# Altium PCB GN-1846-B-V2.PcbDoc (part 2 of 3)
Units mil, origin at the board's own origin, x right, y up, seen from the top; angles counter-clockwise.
Board outline 11621.85 x 2979.29 mil, 2 copper layers (Top, Bottom), stack 12.7 mil thick; 356 components, 252 nets, 1224 pads, 826 vias.
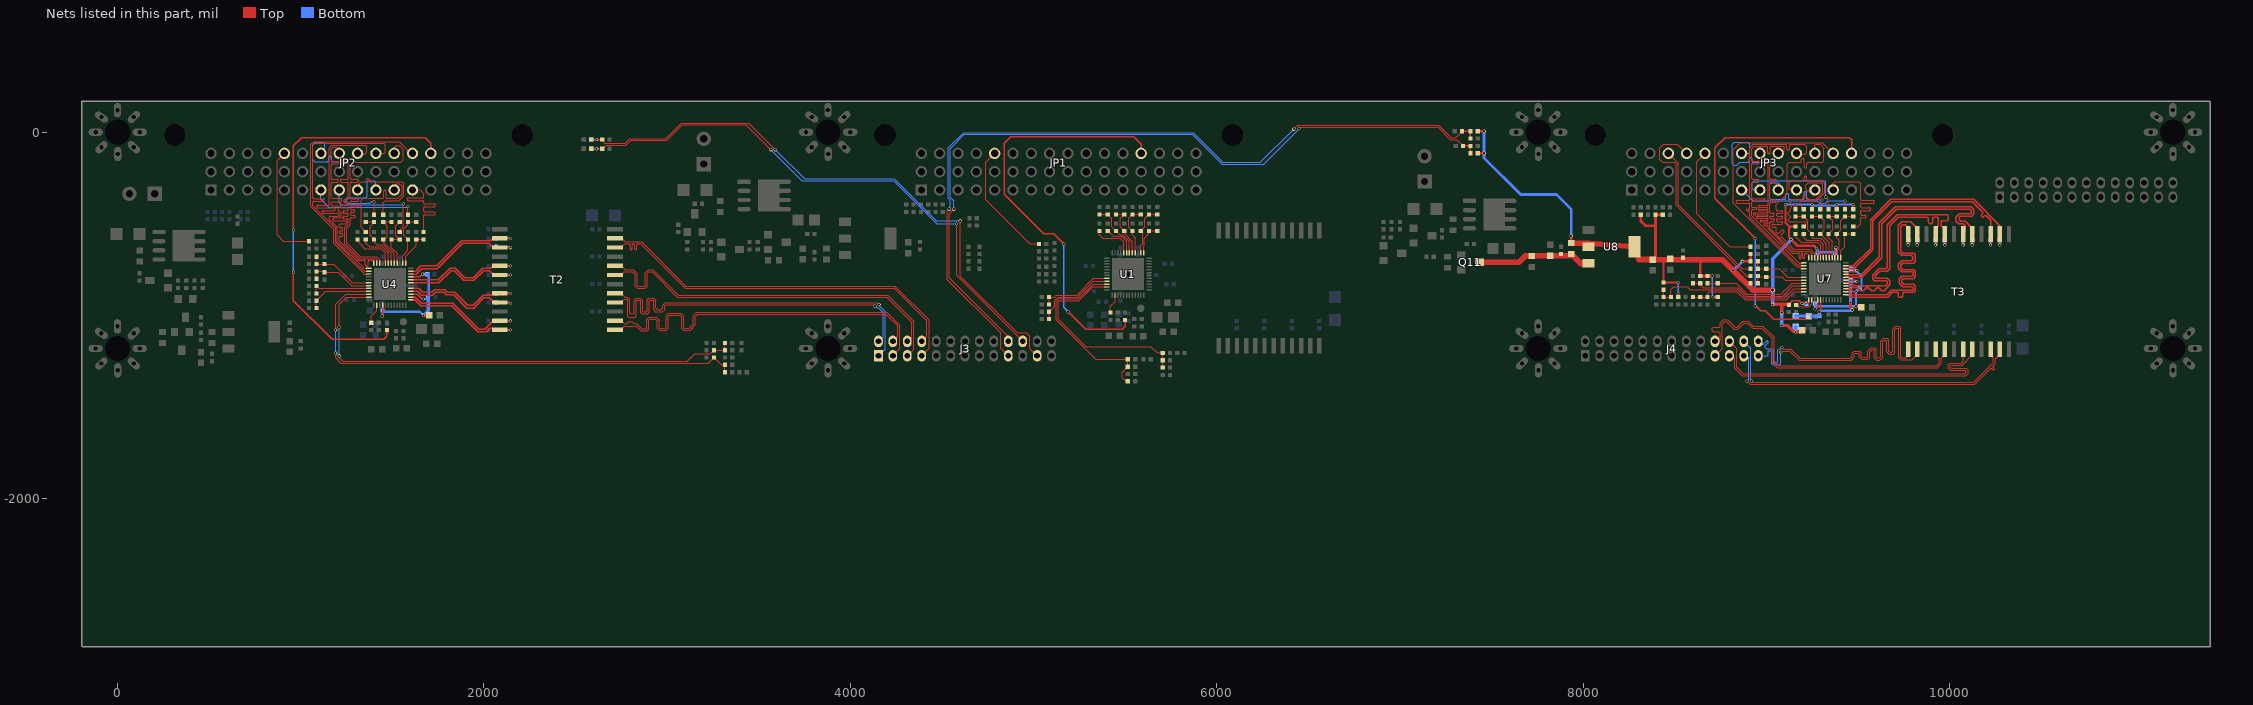
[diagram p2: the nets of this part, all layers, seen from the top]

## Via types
v1: diameter 18, hole 12, Top to Bottom, 786 vias
v2: diameter 24, hole 16, Top to Bottom, 28 vias
v3: diameter 30, hole 20, Top to Bottom, 6 vias
v4: diameter 40, hole 30, Top to Bottom, 6 vias

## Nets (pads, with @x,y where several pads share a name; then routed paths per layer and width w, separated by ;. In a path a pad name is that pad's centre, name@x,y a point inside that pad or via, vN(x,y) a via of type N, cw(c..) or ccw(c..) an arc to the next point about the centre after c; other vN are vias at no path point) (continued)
B_MX1_N: J3.8 T2.22 | length 2112.3
  Top w6: T2.22@2715.76,-629.21 2750,-629.21 2769.21,-610 2792.6,-610 cw(c2792.6,-615.4) 2798,-615.4 2798,-635.5 ccw(c2803.4,-635.5) 2803.4,-640.9 2804.6,-640.9 ccw(c2804.6,-635.5) 2810,-635.5 2810,-615.4 cw(c2815.4,-615.4) 2815.4,-610 2816.6,-610 cw(c2816.6,-615.4) 2822,-615.4 2822,-635.5 ccw(c2827.4,-635.5) 2827.4,-640.9 2828.6,-640.9 ccw(c2828.6,-635.5) 2834,-635.5 2834,-615.4 cw(c2839.4,-615.4) 2839.4,-610 2856.62,-610 3097.62,-851 4238.44,-851 4418,-1030.56 4418,-1113.5 J3.8@4389.76,-1141.73
B_MX1_P: J3.7 T2.23 | length 2109.9
  Top w6: T2.23@2715.76,-579.21 2752.21,-579.21 2772,-599 2861.17,-599 3102.17,-840 4243,-840 4430,-1027 4430,-1180.24 J3.7@4389.76,-1220.47
B_MX2_N: J3.6 T2.19 | length 2003
  Top w6: T2.19@2715.76,-779.21 2750.79,-779.21 2767,-763 2809.09,-763 2825,-778.91 2825,-840.56 2835.44,-851 2879.56,-851 2890,-840.56 2890,-773 2900,-763 2918,-763 3056,-901 4199.44,-901 4335,-1036.56 4335,-1117.76 J3.6@4311.02,-1141.73
B_MX2_P: J3.5 T2.20 | length 2107.2
  Top w6: T2.20@2715.76,-729.21 2749.21,-729.21 2772,-752 2813.65,-752 2836,-774.35 2836,-836 2840,-840 2875,-840 2879,-836 2879,-768.44 2895.44,-752 2922.56,-752 3060.56,-890 4204,-890 4346,-1032 4346,-1185.5 J3.5@4311.02,-1220.47
B_MX3_N: J3.2 T2.16 | length 2043.5
  Top w6: T2.16@2715.76,-929.21 2750.79,-929.21 2767,-913 2778,-913 2785,-920 2785,-1005 2790,-1010 2825,-1010 2830,-1005 2830,-923.4 2835,-918.4 2849.4,-918.4 2856,-925 2856,-986 2860,-990 2895,-990 2901.44,-983.56 2901.44,-923.56 2906.6,-918.4 2923.4,-918.4 2925.56,-920.56 2925.56,-970.56 2936,-981 2974,-981 2986.99,-968.01 2986.99,-948.01 2993,-942 4127,-942 v1(4135,-950)
  Bottom w6: v1(4135,-950) 4143,-958 4151,-958 4179,-986 4179,-1116.28 J3.2@4153.54,-1141.73
B_MX3_P: J3.1 T2.17 | length 2121.5
  Top w6: T2.17@2715.76,-879.21 2749.21,-879.21 2772,-902 2782.56,-902 2796,-915.44 2796,-986 2800,-990 2815,-990 2819,-986 2819,-918.84 2830.44,-907.4 2853.96,-907.4 2867,-920.44 2867,-977 2869,-979 2886,-979 2890.44,-974.56 2890.44,-913.84 2896.89,-907.4 2927.96,-907.4 2936.56,-916 2936.56,-961.56 2945,-970 2965,-970 2975.99,-959.01 2975.99,-943.46 2988.44,-931 4147,-931 v1(4157,-941) ; v1@4159,-939 v1@4160,-940
  Bottom w6: J3.1@4153.54,-1220.47 4190,-1184.02 4190,-981.44 4160,-951.44 4160,-941 v1@4160,-940
B_MX4_N: J3.4 T2.13 | length 1990.4
  Top w6: T2.13@2715.76,-1079.21 2745.79,-1079.21 2767,-1058 2830,-1058 2857,-1085 2890,-1085 2900,-1075 2900,-1025 2905,-1020 2935,-1020 2945,-1030 2945,-1069 2956,-1080 2994,-1080 3005,-1069 3005,-1005 3010,-1000 3070,-1000 3080,-1010 3080,-1070 3090,-1080 3125,-1080 3153,-1052 3153,-1007 3167,-993 4194.44,-993 4259,-1057.56 4259,-1115.02 J3.4@4232.28,-1141.73
B_MX4_P: J3.3 T2.14 | length 2100.2
  Top w6: T2.14@2715.76,-1029.21 2749.21,-1029.21 2767,-1047 2778,-1047 2790,-1035 2808,-1035 2820,-1047 2834.56,-1047 2861.56,-1074 2885,-1074 2889,-1070 2889,-1020.44 2900.44,-1009 2939.56,-1009 2956,-1025.44 2956,-1064.44 2960.56,-1069 2989.44,-1069 2994,-1064.44 2994,-1000.44 3005.44,-989 3074.56,-989 3091,-1005.44 3091,-1065.44 3094.56,-1069 3120.44,-1069 3142,-1047.44 3142,-1002.44 3162.44,-982 4199,-982 4270,-1053 4270,-1182.76 J3.3@4232.28,-1220.47
B_TD1_N: C58.2 T2.3 U4.10 | length 706.2
  Top w8: U4.10@1600.76,-774.09 1630.91,-774.09 1660,-745 1745,-745 1885,-605 2025,-605 2050,-630 2085.05,-630 T2.3@2085.84,-629.21 v1@2144.21,-629.21
  Bottom w8: C58.2@2065,-625 2140,-625 v1(2145,-630)
B_TD1_P: C54.2 T2.2 U4.11 | length 698.8
  Top w8: U4.11@1600.76,-758.34 1626.66,-758.34 1655.42,-729.58 1742.03,-729.58 1879.62,-592 2038,-592 2050.79,-579.21 T2.2@2085.84,-579.21 2144.21,-579.21 v1(2145,-580)
  Bottom w8: C54.2@2065,-580 v1(2145,-580)
B_TD2_N: C57.2 T2.6 U4.7 | length 711
  Top w8: U4.7@1600.76,-821.34 1753.66,-821.34 1820,-755 1836.62,-755 1889.62,-808 1945.38,-808 1998.38,-755 2030,-755 2054.21,-779.21 T2.6@2085.84,-779.21 2145,-779.21 2149.21,-779.21 v1@2150,-780
  Bottom w8: C57.2@2065,-780 v1(2145,-780)
B_TD2_P: C53.2 T2.5 U4.8 | length 700.1
  Top w8: U4.8@1600.76,-805.59 1751.02,-805.59 1814.62,-742 1842,-742 1895,-795 1940,-795 1993,-742 2038,-742 2050.79,-729.21 T2.5@2085.84,-729.21 2144.21,-729.21 v1(2145,-730)
  Bottom w8: C53.2@2065,-730 v1(2145,-730)
B_TD3_N: C52.2 T2.9 U4.4 | length 706.4
  Top w8: U4.4@1600.76,-868.58 1638.58,-868.58 1660,-890 1718.38,-890 1735.38,-873 1779.62,-873 1794.62,-888 1834.62,-888 1906.62,-960 1945,-960 2000,-905 2030,-905 2054.21,-929.21 T2.9@2085.84,-929.21 2139.21,-929.21 v1(2145,-935)
  Bottom w8: C52.2@2065,-930 v1@2140,-930
B_TD3_P: C56.2 T2.8 U4.5 | length 704
  Top w8: U4.5@1600.76,-852.83 1642.83,-852.83 1665,-875 1715,-875 1730,-860 1785,-860 1800,-875 1840,-875 1910,-945 1940,-945 1995,-890 2040,-890 2050.79,-879.21 T2.8@2085.84,-879.21 ; T2.8@2085.05,-880 T2.8@2085.84,-879.21 ; v1@2145.79,-879.21 2145,-879.21 T2.8@2085.84,-879.21
  Bottom w8: C56.2@2065,-880 v1(2145,-880)
B_TD4_N: C55.2 T2.12 U4.1 | length 708.8
  Top w8: U4.1@1600.76,-915.82 1622.44,-915.82 1654.62,-948 1824.62,-948 1966.62,-1090 2015,-1090 2035,-1070 2045,-1070 2054.21,-1079.21 T2.12@2085.84,-1079.21 2144.21,-1079.21 v1(2145,-1080)
  Bottom w8: C55.2@2065,-1080 v1(2145,-1080)
B_TD4_P: C51.2 T2.11 U4.2 | length 716
  Top w8: U4.2@1600.76,-900.08 1625.08,-900.08 1660,-935 1830,-935 1970,-1075 2005,-1075 2050,-1030 2085.05,-1030 T2.11@2085.84,-1029.21 2144.21,-1029.21 v1(2145,-1030)
  Bottom w8: C51.2@2065,-1030 v1(2145,-1030)
BEPHY_CLK: JP2.A13 R73.1 | length 2320.4
  Top w8: v1(960,-765) 960,-920 1171,-1131 1454,-1131 1470,-1115 R73.1@1470,-1080 ; v1(960,-535) 960,-75 1005,-30 1680,-30 1709.84,-59.84 JP2.A13@1709.84,-115.35
  Bottom w8: v1(960,-765) v1(960,-535)
BEPHY_RSTN: JP2.A5 R72.1 | length 650.6
  Top w5: JP2.A5@909.84,-115.35 870,-155.2 870,-560 905,-595 R72.1@1045,-595
BGE0_ENREG: R85.1 U4.38 | length 108.2
  Top w5: R85.1@1385,-1040 1385,-1005 1414.93,-975.07 U4.38@1414.93,-944.17
BGE0_INT_N: R83.1 U4.20 | length 245
  Top w5: R83.1@1310,-585 1310,-595 1350,-635 1440,-635 1462.18,-657.18 U4.20@1462.18,-714.25
BGE0_LED0: R80.1 R81.1 R89.1 U4.34 | length 2694.4
  Top w5: v1@1190,-1200 v1(1190,-1207) 1190,-1232 1218,-1260 3225,-1260 R89.1@3255,-1230 ; v1(1190,-1080) 1190,-940 1245.67,-884.33 U4.34@1370.84,-884.33 ; R89.1@3260,-1235 3295,-1270 R80.1@3315,-1270 R81.1@3315,-1310
  Bottom w5: v1@1190,-1200 v1(1190,-1080)
BGE0_LED1: R75.1 R76.1 R92.1 U4.35 | length 2630.1
  Top w5: v1(1210,-1221) 1210,-1231 1229,-1250 3110,-1250 3150,-1210 3235,-1210 R92.1@3255,-1190 ; v1(1210,-1065) 1210,-940 1249.92,-900.08 U4.35@1370.84,-900.08 ; R92.1@3265,-1190 R76.1@3315,-1190 R75.1@3315,-1150
  Bottom w5: v1@1210,-1215 v1(1210,-1065)
BGE0_LED2: R100.1 R101.1 U4.32 | length 331.2
  Top w5: R101.1@1085,-880 R100.1@1085,-840 1097.83,-852.83 U4.32@1370.84,-852.83
BGE0_PME: R87.1 R88.1 U4.33 | length 347.1
  Top w5: R88.1@1085,-960 R87.1@1085,-920 1136.42,-868.58 U4.33@1370.84,-868.58
BGE0_RXCLK: R64.2 U4.19 | length 221.2
  Top w5: R64.2@1355,-585 1355,-605 1375,-625 1445,-625 1477.93,-657.93 U4.19@1477.93,-714.25
BGE0_RXCTL: R65.2 R93.1 U4.13 | length 204.8
  Top w5: U4.13@1572.41,-702.59 U4.13@1572.41,-714.25 1572.41,-677.59 1630,-620 R93.1@1630,-585 R65.2@1670,-585
BGE0_RXD0: R66.2 R96.1 R98.1 U4.14 | length 299.2
  Top w5: U4.14@1556.67,-714.25 1556.67,-673.33 1585,-645 R98.1@1585,-585 1563,-563 1563,-527 1585,-505 R66.2@1585,-490 R96.1@1630,-490
BGE0_RXD1: R67.2 R102.1 R103.1 U4.16 | length 299.1
  Top w5: U4.16@1525.17,-714.25 1525.17,-660.17 1495,-630 R103.1@1495,-585 R67.2@1540,-585 1519,-564 1519,-511 R102.1@1540,-490
BGE0_RXD2: R68.2 R105.1 R107.1 U4.17 | length 312.1
  Top w5: R105.1@1495,-490 R68.2@1450,-490 1472,-512 1472,-568 1450,-590 1450,-600 1509.42,-659.42 U4.17@1509.42,-714.25
BGE0_RXD3: R70.2 R108.1 R109.1 U4.18 | length 346.3
  Top w5: R108.1@1355,-490 R70.2@1400,-490 1378,-512 1378,-563 R109.1@1400,-585 1400,-600 1415,-615 1449.14,-615 1493.67,-659.53 U4.18@1493.67,-714.25
BMAC_MDC: C66.2 R90.1 R97.2 U4.30 | length 367.8
  Top w5: R90.1@1085,-680 R97.2@1085,-720 C66.2@1130,-720 1180,-720 1281.34,-821.34 U4.30@1370.84,-821.34
BMAC_MDIO: C67.2 R91.1 R99.2 U4.31 | length 357.8
  Top w5: R91.1@1085,-800 R99.2@1085,-760 1125,-760 C67.2@1130,-765 1205,-765 1277.08,-837.08 U4.31@1370.84,-837.08
BPHY105: B5.1 C42.1 C43.1 C44.1 U4.3 U4.9 U4.40 | length 795.5
  Top w8: v1(1445,-1005) 1446.43,-1003.57 U4.40@1446.43,-944.17 ; U4.3@1600.76,-884.33 1634.33,-884.33 1660,-910 v1(1670,-910) ; U4.9@1600.76,-789.84 1650.16,-789.84 v1(1665,-775)
  Top w18: v1(1670,-1000) B5.1@1690.47,-1000
  Bottom w8: v1(1445,-1005) v1@1446.43,-1003.57
  Bottom w12: v1@1446.43,-1003.57 C42.1@1446.43,-973.7 1452.73,-980 1650,-980 v1(1670,-1000) ; v1(1665,-775) C44.1@1695,-775 ; v1(1670,-910) 1685,-910 C43.1@1695,-900
  Bottom w15: C44.1@1695,-775 1698,-778 C43.1@1698,-897
  Bottom w18: v1(1670,-1000) 1695,-975 C43.1@1695,-900 C43.1@1698,-897
BRGMII_RXCK: JP2.C11 R64.1 | length 620.5
  Top w5: R64.1@1355,-545 1330,-520 1330,-372 1340.69,-361.31 1444.75,-361.31 ccw(c1444.75,-354.56) 1451.5,-354.56 1451.5,-323.06 cw(c1458.25,-323.06) 1458.25,-316.31 1459.75,-316.31 cw(c1459.75,-323.06) 1466.5,-323.06 1466.5,-354.56 ccw(c1473.25,-354.56) 1473.25,-361.31 1529.55,-361.31 1553,-337.86 1553,-295 1538,-280 1520,-280 1509.84,-290.16 JP2.C11@1509.84,-315.35
BRGMII_RXD0: JP2.C7 R66.1 | length 589.5
  Top w5: R66.1@1585,-450 v1(1585,-405)
  Bottom w5: JP2.C7@1109.84,-315.35 1109.84,-365.34 1153,-408.5 1581.5,-408.5 v1(1585,-405)
BRGMII_RXD1: JP2.C8 R67.1 | length 580.8
  Top w5: R67.1@1540,-535 1560,-515 v1(1560,-390)
  Bottom w5: JP2.C8@1209.84,-315.35 1209.84,-385.43 1220.91,-396.5 1553.5,-396.5 v1(1560,-390)
BRGMII_RXD2: JP2.C9 R68.1 | length 568.8
  Top w5: JP2.C9@1309.84,-315.35 1320,-305.2 1320,-282 1332,-270 1351.75,-270 ccw(c1351.75,-263.25) 1358.5,-263.25 1358.5,-261.75 cw(c1365.25,-261.75) 1365.25,-255 1366.75,-255 cw(c1366.75,-261.75) 1373.5,-261.75 1373.5,-263.25 ccw(c1380.25,-263.25) 1380.25,-270 1553,-270 1563,-280 1563,-347 1535,-375 1460,-375 1450,-385 R68.1@1450,-450
BRGMII_RXD3: JP2.C10 R70.1 | length 539.3
  Top w5: R70.1@1400,-450 v1@1400,-385
  Bottom w5: v1@1400,-385 v1(1400,-380) 1382,-380 1375.5,-386.5 1254.5,-386.5 1247,-379 1247,-363 1252,-358 1354,-358 1362,-350 1362,-271 1368,-265 1400,-265 1409.84,-274.84 JP2.C10@1409.84,-315.35 JP2.C10@1410,-315.51
BRGMII_RXDV: JP2.C12 R65.1 | length 676.3
  Top w5: JP2.C12@1609.84,-315.35 1650.35,-315.35 1670,-335 1670,-357 cw(c1668.5,-357) 1668.5,-358.5 1586.75,-358.5 ccw(c1586.75,-365.25) 1580,-365.25 1580,-366.75 ccw(c1586.75,-366.75) 1586.75,-373.5 1663.25,-373.5 cw(c1663.25,-380.25) 1670,-380.25 1670,-384.75 ccw(c1676.75,-384.75) 1676.75,-391.5 1728.25,-391.5 cw(c1728.25,-398.25) 1735,-398.25 1735,-399.75 cw(c1728.25,-399.75) 1728.25,-406.5 1676.75,-406.5 ccw(c1676.75,-413.25) 1670,-413.25 1670,-428.75 ccw(c1676.75,-428.75) 1676.75,-435.5 1728.25,-435.5 cw(c1728.25,-442.25) 1735,-442.25 1735,-443.75 cw(c1728.25,-443.75) 1728.25,-450.5 1675.5,-450.5 ccw(c1675.5,-456) 1670,-456 R65.1@1670,-535
BRGMII_TXCKOUT: JP2.A11 U4.22 | length 1440.1
  Top w5: U4.22@1430.68,-714.25 1430.68,-695.68 1415,-680 1325.71,-680 1250,-604.29 1250,-524.14 1270,-504.14 1270,-474.25 cw(c1276.75,-474.25) 1276.75,-467.5 1289.75,-467.5 ccw(c1289.75,-460.75) 1296.5,-460.75 1296.5,-459.25 ccw(c1289.75,-459.25) 1289.75,-452.5 1276.75,-452.5 cw(c1276.75,-445.75) 1270,-445.75 1270,-444.25 cw(c1276.75,-444.25) 1276.75,-437.5 1287.14,-437.5 ccw(c1287.14,-430.75) 1293.89,-430.75 1293.89,-429.25 ccw(c1287.14,-429.25) 1287.14,-422.5 1276.75,-422.5 cw(c1276.75,-415.75) 1270,-415.75 1270,-414.25 cw(c1276.75,-414.25) 1276.75,-407.5 1308.25,-407.5 ccw(c1308.25,-400.75) 1315,-400.75 1315,-399.25 ccw(c1308.25,-399.25) 1308.25,-392.5 1276.75,-392.5 cw(c1276.75,-385.75) 1270,-385.75 1270,-384.25 cw(c1276.75,-384.25) 1276.75,-377.5 1308.25,-377.5 ccw(c1308.25,-370.75) 1315,-370.75 1315,-369.25 ccw(c1308.25,-369.25) 1308.25,-362.5 1276.75,-362.5 cw(c1276.75,-355.75) 1270,-355.75 1270,-279.25 cw(c1276.75,-279.25) 1276.75,-272.5 1308.25,-272.5 ccw(c1308.25,-265.75) 1315,-265.75 1315,-264.25 ccw(c1308.25,-264.25) 1308.25,-257.5 1276.75,-257.5 cw(c1276.75,-250.75) 1270,-250.75 1270,-180 1285,-165 1545,-165 1560,-150 1560,-95 1540,-75 1520,-75 1509.84,-85.16 JP2.A11@1509.84,-115.35 JP2.A11@1515,-110.2
BRGMII_TXD0: JP2.A7 U4.23 | length 1443.8
  Top w5: v1(1250,-160) 1260,-170 1260,-250.75 cw(c1253.25,-250.75) 1253.25,-257.5 1221.75,-257.5 ccw(c1221.75,-264.25) 1215,-264.25 1215,-265.75 ccw(c1221.75,-265.75) 1221.75,-272.5 1253.25,-272.5 cw(c1253.25,-279.25) 1260,-279.25 1260,-360.75 cw(c1253.25,-360.75) 1253.25,-367.5 1241.7,-367.5 ccw(c1241.7,-374.25) 1234.95,-374.25 1234.95,-375.75 ccw(c1241.7,-375.75) 1241.7,-382.5 1257.5,-382.5 cw(c1257.5,-385) 1260,-385 1260,-390.75 cw(c1253.25,-390.75) 1253.25,-397.5 1221.75,-397.5 ccw(c1221.75,-404.25) 1215,-404.25 1215,-405.75 ccw(c1221.75,-405.75) 1221.75,-412.5 1253.25,-412.5 cw(c1253.25,-419.25) 1260,-419.25 1260,-420.75 cw(c1253.25,-420.75) 1253.25,-427.5 1236.75,-427.5 ccw(c1236.75,-434.25) 1230,-434.25 1230,-435.75 ccw(c1236.75,-435.75) 1236.75,-442.5 1253.25,-442.5 cw(c1253.25,-449.25) 1260,-449.25 1260,-450.75 cw(c1253.25,-450.75) 1253.25,-457.5 1236.75,-457.5 ccw(c1236.75,-464.25) 1230,-464.25 1230,-465.75 ccw(c1236.75,-465.75) 1236.75,-472.5 1253.25,-472.5 cw(c1253.25,-479.25) 1260,-479.25 1260,-500 1240,-520 1240,-608.43 1321.57,-690 1410.86,-690 1414.93,-694.07 U4.23@1414.93,-714.25
  Bottom w5: JP2.A7@1109.84,-115.35 1130,-95.2 1130,-61.5 1123.5,-55 1075,-55 1065,-65 1065,-150 1075,-160 1145.75,-160 ccw(c1145.75,-153.25) 1152.5,-153.25 1152.5,-136.75 cw(c1159.25,-136.75) 1159.25,-130 1160.75,-130 cw(c1160.75,-136.75) 1167.5,-136.75 1167.5,-157.5 ccw(c1170,-157.5) 1170,-160 v1(1250,-160)
BRGMII_TXD1: JP2.A8 U4.24 | length 1406
  Top w5: JP2.A8@1209.84,-115.35 1209.84,-96.34 1195,-81.5 1175,-81.5 1165,-91.5 1165,-150.75 ccw(c1171.75,-150.75) 1171.75,-157.5 1223.25,-157.5 cw(c1223.25,-164.25) 1230,-164.25 1230,-165.75 cw(c1223.25,-165.75) 1223.25,-172.5 1171.75,-172.5 ccw(c1171.75,-179.25) 1165,-179.25 1165,-250.75 ccw(c1171.75,-250.75) 1171.75,-257.5 1198.25,-257.5 cw(c1198.25,-264.25) 1205,-264.25 1205,-265.75 cw(c1198.25,-265.75) 1198.25,-272.5 1171.75,-272.5 ccw(c1171.75,-279.25) 1165,-279.25 1165,-355 1170,-360 1220,-360 1224.13,-364.13 1224.13,-375 1219.13,-380 1170,-380 1165.33,-384.67 1165.33,-395.82 1171.19,-401.68 1200.85,-401.68 1204.18,-405 1204.18,-426.02 1220.33,-442.18 1220.33,-445 ; 1220,-445 1220,-460.75 cw(c1213.25,-460.75) 1213.25,-467.5 1181.75,-467.5 ccw(c1181.75,-474.25) 1175,-474.25 1175,-475.75 ccw(c1181.75,-475.75) 1181.75,-482.5 1195,-482.5 1195.33,-482.83 1247.83,-482.83 1250,-485 1250,-495 1245,-500 1215,-500 1210,-505 1210,-515.75 ccw(c1216.75,-515.75) 1216.75,-522.5 1223.25,-522.5 cw(c1223.25,-529.25) 1230,-529.25 1230,-530.75 cw(c1223.25,-530.75) 1223.25,-537.5 1216.75,-537.5 ccw(c1216.75,-544.25) 1210,-544.25 1210,-545.75 ccw(c1216.75,-545.75) 1216.75,-552.5 1223.25,-552.5 cw(c1223.25,-559.25) 1230,-559.25 1230,-560.75 cw(c1223.25,-560.75) 1223.25,-567.5 1216.75,-567.5 ccw(c1216.75,-574.25) 1210,-574.25 1210,-592.57 1317.43,-700 1345.75,-700 cw(c1345.75,-706.75) 1352.5,-706.75 1352.5,-724.35 ccw(c1359.25,-724.35) 1359.25,-731.1 1360.75,-731.1 ccw(c1360.75,-724.35) 1367.5,-724.35 1367.5,-706.75 cw(c1374.25,-706.75) 1374.25,-700 1395,-700 1399.19,-704.19 U4.24@1399.19,-714.25
BRGMII_TXD2: JP2.A9 U4.25 | length 1416.9
  Top w5: JP2.A9@1309.84,-115.35 1314.49,-120 1350,-120 1360,-110 1360,-80 1351.5,-71.5 1168.5,-71.5 1155,-85 1155,-390.75 cw(c1148.25,-390.75) 1148.25,-397.5 1094.44,-397.5 ccw(c1094.44,-404.25) 1087.69,-404.25 1087.69,-405.75 ccw(c1094.44,-405.75) 1094.44,-412.5 1180.56,-412.5 cw(c1180.56,-419.25) 1187.31,-419.25 1187.31,-420.75 cw(c1180.56,-420.75) 1180.56,-427.5 1124.44,-427.5 ccw(c1124.44,-434.25) 1117.69,-434.25 1117.69,-435.75 ccw(c1124.44,-435.75) 1124.44,-442.5 1203.25,-442.5 cw(c1203.25,-449.25) 1210,-449.25 1210,-450.75 cw(c1203.25,-450.75) 1203.25,-457.5 1161.75,-457.5 ccw(c1161.75,-464.25) 1155,-464.25 1155,-475 1200,-520 1200,-596.72 1345.89,-742.6 U4.25@1370.84,-742.6
BRGMII_TXD3: JP2.A10 U4.26 | length 1438.7
  Top w5: U4.26@1370.84,-758.34 1347.48,-758.34 1190,-600.86 1190,-525.47 1065,-400.47 1065,-384.25 cw(c1071.75,-384.25) 1071.75,-377.5 1122,-377.5 ccw(c1122,-370.75) 1128.75,-370.75 1128.75,-369.25 ccw(c1122,-369.25) 1122,-362.5 1071.75,-362.5 cw(c1071.75,-355.75) 1065,-355.75 1065,-70.64 1074.14,-61.5 1451.5,-61.5 1460,-70 1460,-110 1454.65,-115.35 JP2.A10@1409.84,-115.35
BRGMII_TXEN: JP2.A12 U4.27 | length 1438.7
  Top w5: U4.27@1370.84,-774.09 1349.09,-774.09 1180,-605 1180,-529.61 1055,-404.61 1055,-66.5 1070,-51.5 1536.5,-51.5 1600.35,-115.35 JP2.A12@1609.84,-115.35
BUART1_RXD: J3.23 R112.2 R201.1 R202.1 | length 3262.6
  Top w5: R112.2@2585,-40 v1(2615,-40) R202.1@2645,-40 2645,-45 2660,-60 2770.86,-60 2795.86,-35 2992.57,-35 3077.57,50 3445,50 v1(3590,-95) ; v1(4600,-484) 4600,-785 4910,-1095 4960,-1095 4980,-1115 4980,-1180.79 J3.23@5019.69,-1220.47
  Bottom w5: v1(3590,-95) 3750,-255 4240,-255 4469,-484 v1(4600,-484)
  Bottom w8: R201.1@2585,-40 v1(2615,-40)
BUART1_TXD: J3.22 R114.2 R200.1 R203.1 | length 3093.2
  Top w5: R114.2@2585,-90 v1(2615,-90) R203.1@2645,-90 2647,-90 2667,-70 2775,-70 2800,-45 2996.72,-45 3081.72,40 3430,40 v1(3565,-95) ; v1(4580,-501) 4580,-780.79 J3.22@4940.95,-1141.73
  Bottom w5: v1(3565,-95) 3735,-265 4235.86,-265 4471.86,-501 v1(4580,-501)
  Bottom w8: R200.1@2585,-90 v1(2615,-90)
C3V3A: B9.1 C82.1 C83.1 C84.1 U7.6 U7.41 | length 661.8
  Top w8: v1(9290,-980) 9296.42,-973.58 U7.41@9296.42,-915.59 ; U7.6@9434.96,-807.87 9487.87,-807.87 9488.5,-808.5 ; 9487.87,-808.5 9488.5,-808.5 ; v1(9495,-815) 9488.5,-808.5
  Top w15: v1(9460,-930) 9460,-960 v1(9470,-970)
  Bottom w12: C82.1@9460.2,-815 v1(9495,-815)
  Bottom w15: B9.1@9161,-1003.47 9161.53,-1004 9233,-1004 C83.1@9290,-1004 v1(9290,-980) 9295,-975 9465,-975 v1(9470,-970) ; v1(9460,-930) C82.1@9460,-815.2
C3V3D: B7.2 B9.2 C72.1 C73.1 C74.1 C75.1 C96.1 C97.1 R131.1 R134.1 R139.1 R143.2 R144.1 R145.2 R147.2 R149.2 R150.2 R151.2 R156.2 R160.2 R162.2 R165.2 R168.2 R210.2 R211.2 R315.2 R316.2 R317.2 U7.15 U7.21 U7.37 U8.2 U8.4 | length 5371.1
  Top w8: R145.2@9121,-940 9141,-920 9180,-920 v1(9195,-935) 9225,-935 9233.39,-926.61 U7.37@9233.39,-914.96 ; U7.21@9280.63,-685.04 v1@9280.63,-640.63 ; U7.21@9280.67,-685.67 U7.21@9280.67,-685.04 ; U7.15@9375,-685.04 9375,-685.51 U7.15@9375.16,-685.67 ; U7.15@9375.12,-685.04 9375.12,-634.88 v1(9380,-630)
  Top w10: 8440,-700 R149.2@8440,-820 v1(8520,-820) ; v1(8710,-900) R134.1@8735,-900
  Top w12: R139.1@8520,-900 v1(8520,-880) ; v1(9105,-395) 9105,-495 9125,-515 9125,-525 ; R145.2@9121,-940 R145.2@9124,-943 ; v1(9135,-585) 9125,-575 9125,-525 ; R143.2@9160,-515 9135,-515 9125,-525 ; R168.2@9160,-420 v1(9160,-395) ; R165.2@9250,-420 v1(9250,-395) ; R162.2@9385,-420 v1@9385,-400 ; R156.2@9475,-420 v1@9475,-400
  Top w15: R211.2@7425,-115 v1(7460,-115) ; R210.2@7425,5 v1(7460,5) ; R144.1@7935,-605 v1(7935,-565) ; R315.2@8315,-450 8315,-485 8340,-510 8395,-510 ; C75.1@8380,-695.47 8380.47,-695 8395,-680.47 8395,-510 ; R317.2@8435,-450 R316.2@8395,-450 8395,-510 ; 8640,-700 R147.2@8640,-785 R160.2@8680,-785 v1(8705,-785) ; v1(8870,-705) R150.2@8915,-705 R131.1@8915,-665 ; v1(9135,-585) 9170,-620 9260,-620 v1(9275,-635)
  Top w18: v1(9035,-940) 9085,-940 ; v1(9085,-1055) 9115,-1055 9147.47,-1087.47 ; v1(9085,-985) 9085,-940 ; R145.2@9121,-940 9085,-940 ; v1(9160,-1090) 9185.47,-1090 B7.2@9195.47,-1080
  Top w30: R144.1@7940,-605 8030,-605 8031.59,-605.13 U8.4@8274.1,-624.53 ; U8.4@8270,-624.53 U8.4@8274.1,-624.53 ; U8.4@8280,-625 U8.4@8274.1,-624.53 ; U8.4@8280,-624.53 U8.4@8274.1,-624.53 ; 8305,-695 C75.1@8375,-695 ; 8305,-694.53 C75.1@8380,-694.53 ; C75.1@8380.47,-695 8475,-695 8760,-695 v1(8820,-755) 8927.5,-862.5 v2(9035,-862.5)
  Bottom w10: v1(8520,-880) v1(8520,-820) ; v1(8705,-785) 8705,-895 v1(8710,-900)
  Bottom w12: v1(9105,-395) v1(9160,-395) v1(9250,-395) ; v1@9196,-936 C74.1@9220,-936 ; v1@9255,-400 v1@9380,-400 ; v1(9385,-395) v1(9475,-395)
  Bottom w15: v1(7460,5) v1(7460,-115) 7460,-140 7660,-340 7855,-340 7935,-420 v1(7935,-565) ; v1(8820,-755) v1(8870,-705) ; v1(9275,-635) 9280.67,-640.67 C73.1@9280.67,-655.47 ; C73.1@9280,-655.47 C73.1@9280.67,-655.47 ; C73.1@9280.67,-660 C73.1@9280.67,-655.47 ; C72.1@9375,-660 9380,-655 v1(9380,-630) ; C72.1@9375,-655.47 C73.1@9280.67,-655.47
  Bottom w18: v1(9035,-940) v2(9035,-862.5) 9035,-690 v1@9135,-590 ; v1(9085,-1055) v1(9085,-985) ; v1(9160,-1090) 9160,-1063.53 B9.2@9161,-1062.53
C5V: C98.1 C99.1 Q11.3 R144.2 R146.1 U8.3 | length 625.3
  Top w32: Q11.3@7435,-710 7650,-710 7685.47,-674.53 7720,-674.53 C99.1@7820,-674.53 R144.2@7929.53,-674.53 ; R144.2@7935,-665 7986,-716 U8.3@8030,-716
C_MCLK: JP3.A3 R157.1 | length 842.1
  Top w5: JP3.A3@8465.75,-115.35 8520,-169.61 8520,-395 8870,-745 R157.1@8915,-745
C_MDIO: JP3.A4 R159.1 | length 1129.7
  Top w5: JP3.A4@8565.75,-115.35 8515.39,-65 8440,-65 8420,-85 8420,-150 8435,-165 8500,-165 8510,-175 8510,-400 8895,-785 R159.1@8915,-785
C_MX1_N: J4.24 T3.22 | length 1687
  Top w6: v1(8920,-1360) 8926,-1366 10132.16,-1366 10211.61,-1286.55 10239.72,-1258.44 10239.72,-1229.72 10225,-1215 T3.22@10225,-1184.96
  Top w8: T3.22@10225,-1220 T3.22@10225,-1215
  Bottom w6: J4.24@8877.95,-1141.73 8915,-1178.78 8915,-1355 v1(8920,-1360)
C_MX1_P: J4.23 T3.23 | length 1687.8
  Top w6: v1(8895,-1360) 8912,-1377 10138,-1377 10223.52,-1291.48 cw(c10227.34,-1295.3) 10231.16,-1291.48 10235.72,-1296.04 ccw(c10239.53,-1292.22) 10243.35,-1296.04 10244.2,-1295.19 ccw(c10240.38,-1291.37) 10244.2,-1287.55 10239.64,-1282.99 cw(c10243.46,-1279.18) 10239.64,-1275.36 10250.72,-1264.28 10250.72,-1239.28 10275,-1215 T3.23@10275,-1184.96
  Bottom w6: J4.23@8877.95,-1220.47 8894.47,-1220.47 8904,-1230 8904,-1351 v1(8895,-1360)
C_MX2_N: J4.22 T3.19 | length 1709.3
  Top w6: J4.22@8799.21,-1141.73 8840,-1182.52 8840,-1284.44 8874.56,-1319 10086,-1319 10090,-1315 10090,-1304.4 10084.28,-1298.68 10005.12,-1298.68 9995,-1288.56 9995,-1270 10005,-1260 10064.44,-1260 10075,-1249.44 T3.19@10075,-1184.96
C_MX2_P: J4.21 T3.20 | length 1689.9
  Top w6: J4.21@8799.21,-1220.47 8814.47,-1220.47 8829,-1235 8829,-1289 8870,-1330 10090.56,-1330 10101.91,-1318.65 10101.91,-1298.06 10091.53,-1287.68 10009.68,-1287.68 10006,-1284 10006,-1274.56 10009.56,-1271 10069,-1271 10125,-1215 T3.20@10125,-1184.96
C_MX3_N: J4.20 T3.16 | length 1697.5
  Top w6: J4.20@8720.47,-1141.73 8743.27,-1141.73 8749,-1136 8749,-1100 8739,-1090 8710,-1090 8705,-1085 8705,-1070 8710,-1065 8744,-1065 8749,-1060 8749,-1041 8766,-1024 8790,-1024 8830,-1064 8841,-1064 8873,-1032 8903,-1032 8930,-1059 8981.56,-1059 9043,-1120.44 9043,-1250.83 9066.17,-1274 9930.44,-1274 9945,-1259.44 9945,-1235 T3.16@9925,-1215
  Top w8: T3.16@9925,-1215 T3.16@9925,-1184.96
C_MX3_P: J4.19 T3.17 | length 1697.1
  Top w6: J4.19@8720.47,-1220.47 8760,-1180.95 8760,-1045.56 8770.56,-1035 8785.44,-1035 8825.44,-1075 8845.56,-1075 8877.56,-1043 8898.44,-1043 8925.44,-1070 8977,-1070 9032,-1125 9032,-1255.38 9034.9,-1258.29 ; 9037.32,-1260.7 9034.9,-1258.29 ; T3.17@9975,-1184.96 9975,-1215 9956,-1234 9956,-1264 9935,-1285 9061.62,-1285 9034.9,-1258.29
C_MX4_N: J4.26 T3.13 | length 1693.1
  Top w6: v1(9085,-1175) 9094,-1184 9134,-1184 9185,-1235 9460,-1235 9470,-1225 9470,-1205 9480,-1195 9510,-1195 9520,-1205 9520,-1222 9527,-1229 9548,-1229 9554,-1223 9554,-1195.44 9573.19,-1176.25 9591.25,-1176.25 9601,-1186 9601,-1228 9605,-1232 9618,-1232 9624,-1226 9624,-1140.44 9639.44,-1125 9660,-1125 9670,-1135 9670,-1195 9676.6,-1201.6 9685,-1201.6 9690,-1196.6 9690,-1075 9705,-1060 9725.56,-1060 9735,-1069.44 9735,-1227 9740,-1232 9763,-1232 9775,-1220 T3.13@9775,-1184.96
  Bottom w6: J4.26@8956.69,-1141.73 8961.73,-1141.73 8977.04,-1157.04 ccw(c8980.86,-1153.22) 8984.68,-1157.04 9001.79,-1139.93 cw(c9005.61,-1143.75) 9009.43,-1139.93 9010.27,-1140.78 cw(c9006.46,-1144.6) 9010.27,-1148.41 8993.16,-1165.53 ccw(c8996.98,-1169.34) 8993.16,-1173.16 9002.07,-1182.07 9029.56,-1182.07 9041,-1193.52 ; 9041,-1199.52 9041,-1193.52 ; v1@9078.83,-1181.17 9070,-1181.17 9063,-1188.17 9063,-1256 9060,-1259 9045,-1259 9041,-1255 9041,-1193.52
C_MX4_P: J4.25 T3.14 | length 1685.1
  Top w6: v1@9085,-1195 9129.44,-1195 9180.44,-1246 9464.56,-1246 9481,-1229.56 9481,-1209.56 9484.56,-1206 9505.44,-1206 9509,-1209.56 9509,-1226.56 9522.44,-1240 9555,-1240 9565,-1230 9565,-1200 9577.75,-1187.25 9586.7,-1187.25 9590,-1190.56 9590,-1232.56 9602.44,-1245 9620.56,-1245 9635,-1230.56 9635,-1145 9644,-1136 9655.44,-1136 9659,-1139.56 9659,-1199.56 9672.04,-1212.6 9692.96,-1212.6 9701,-1204.56 9701,-1079.56 9709.56,-1071 9721,-1071 9724,-1074 9724,-1231.56 9735.44,-1243 9797,-1243 9825,-1215 T3.14@9825,-1184.96
  Bottom w6: J4.25@8956.69,-1220.47 9004.53,-1220.47 9010,-1215 9010,-1195 9011.93,-1193.07 9025,-1193.07 9030,-1198.07 9030,-1265 9035,-1270 9075,-1270 9080,-1265 v1(9080,-1200)
C_TD1_N: C87.2 T3.3 U7.10 | length 1272.3
  Top w8: U7.10@9435,-745.51 9477.87,-745.51 9583,-640.38 9583,-482 9685,-380 10125,-380 10180.31,-435.31 cw(c10175.22,-440.4) 10180.31,-445.49 10175.99,-449.82 ccw(c10181.08,-454.91) 10175.99,-460 10177.12,-461.13 ccw(c10182.21,-456.04) 10187.3,-461.13 10191.62,-456.81 cw(c10196.72,-461.9) 10201.81,-456.81 10225,-480 ; v1(10225,-615) T3.3@10225,-555.04 10225,-480 ; 10225,-488 10225,-480
  Bottom w8: v1(10225,-615) C87.2@10225,-590
C_TD1_P: C93.2 T3.2 U7.11 | length 1272.3
  Top w8: U7.11@9435,-729.76 9475.24,-729.76 9570,-635 9570,-476.62 9679.62,-367 10132,-367 10275,-510 T3.2@10275,-555.04 v1(10275,-615)
  Bottom w8: v1(10275,-615) C93.2@10275,-590
C_TD2_N: C91.2 T3.6 U7.7 | length 1275.9
  Top w8: U7.7@9435,-792.76 9522.24,-792.76 9630,-685 9630,-500 9710,-420 10115,-420 10120,-425 10120,-440 10115,-445 10055,-445 10035,-465 10035,-485 10050,-500 10075.86,-500 10085.86,-510 10085.86,-544.18 T3.6@10075,-555.04 v1(10075,-615)
  Bottom w8: v1(10075,-615) C91.2@10075,-590
C_TD2_P: C92.2 T3.5 U7.8 | length 1297.6
  Top w8: U7.8@9435,-777.01 9519.61,-777.01 9617,-679.62 9617,-494.62 9704.62,-407 10120.38,-407 10133,-419.62 10133,-446.44 10121.44,-458 10060.38,-458 10054.19,-464.19 10054.19,-479.19 10062,-487 10087,-487 10125,-525 T3.5@10125,-555.04 v1(10125,-615)
  Bottom w8: v1(10125,-615) C92.2@10125,-590
C_TD3_N: C89.2 T3.9 U7.4 | length 1251.6
  Top w8: U7.4@9434.96,-839.37 9464.37,-839.37 9475,-850 9500,-850 9515,-865 9530,-865 9545,-850 9560,-850 9575,-865 9590,-865 9605,-850 9615,-850 9630,-865 9643.38,-865 9675,-833.38 9675,-810 9662,-797 9600.38,-797 9595.38,-792 9595.38,-784.62 9620.38,-759.62 9660.38,-759.62 9675,-745 9675,-510 9720,-465 9875.15,-465 cw(c9875.15,-475.35) 9885.5,-475.35 9885.5,-489.65 ccw(c9895.85,-489.65) 9895.85,-500 9898.15,-500 ccw(c9898.15,-489.65) 9908.5,-489.65 9908.5,-475.35 cw(c9918.85,-475.35) 9918.85,-465 9935,-465 9940,-470 9940,-510 9925,-525 T3.9@9925,-555.04 v1(9925,-615)
  Bottom w8: v1(9925,-615) C89.2@9925,-590
C_TD3_P: C90.2 T3.8 U7.5 | length 1272.2
  Top w8: U7.5@9434.96,-823.62 9467,-823.62 9480.38,-837 9653,-837 9662,-828 9662,-817 9655,-810 9590,-810 9581,-801 9581,-780.62 9615,-746.62 9653.38,-746.62 9662,-738 9662,-504.62 9716.62,-450 9990,-450 9995,-455 9995,-474.8 cw(c9987.8,-474.8) 9987.8,-482 9962.2,-482 ccw(c9962.2,-489.2) 9955,-489.2 9955,-510 9975,-530 T3.8@9975,-555.04 v1(9975,-615)
  Bottom w8: v1(9975,-615) C90.2@9975,-590
C_TD4_N: C86.2 T3.12 U7.1 | length 1281.4
  Top w8: U7.1@9447.24,-887.24 9461,-901 9662.38,-901 9688.38,-875 9715,-875 9720,-880 9720,-895 9725,-900 9740,-900 9745,-895 9745,-880 9750,-875 9805,-875 9815,-865 9815,-840 9805,-830 9750,-830 9740,-820 9740,-805 9745,-800 9805,-800 9815,-790 9815,-760 9805,-750 9745,-750 9735,-740 9735,-725 9745,-715 9805,-715 9815,-705 9815,-670 9805,-660 9745,-660 9735,-650 9735,-515 9745,-505 9760,-505 9775,-520 T3.12@9775,-555.04 v1(9775,-615)
  Bottom w8: v1(9775,-615) C86.2@9775,-590
C_TD4_P: C88.2 T3.11 U7.2 | length 1297.2
  Top w8: U7.2@9434.96,-870.87 9450.87,-870.87 ; 9451.5,-871.5 9468,-888 9657,-888 9683,-862 9798,-862 9802,-858 9802,-847 9798,-843 9744.62,-843 9727,-825.38 9727,-799.62 9739.62,-787 9798,-787 9802,-783 9802,-767 9798,-763 9739.62,-763 9722,-745.38 9722,-719.62 9739.62,-702 9793,-702 9799.62,-695.38 9799.62,-680 9792.62,-673 9739.62,-673 9722,-655.38 9722,-508 9740,-490 9790,-490 9825,-525 T3.11@9825,-555.04 v1(9825,-615)
  Bottom w8: v1(9825,-615) C88.2@9825,-590
CEPHY_CLK: JP3.A13 R133.1 | length 2122.5
  Top w8: v1(8940,-580) 8720,-360 8720,-85 8776,-29 9453.54,-29 9465.75,-41.2 JP3.A13@9465.75,-115.35 ; v1@8942,-947 8970,-975 8995,-975 9040,-1020 9218,-1020 R133.1@9230,-1008
  Bottom w8: v1@8940,-945 v1(8940,-580)
  other v1: 8940,-949
CEPHY_RSTN: JP3.A5 R132.1 | length 718.2
  Top w5: JP3.A5@8665.75,-115.35 8620,-161.1 8620,-445 8800,-625 R132.1@8915,-625
CGE0_ENREG: R145.1 U7.38 | length 115.4
  Top w5: R145.1@9164,-943 9172.5,-951.5 9233.5,-951.5 9249.17,-935.83 U7.38@9249.17,-915.59
CGE0_INT_N: R143.1 U7.20 | length 239.9
  Top w5: R143.1@9160,-555 9160,-570 9190,-600 9280,-600 9296.42,-616.42 U7.20@9296.38,-685.04 U7.20@9296.42,-685.67
CGE0_LED0: R140.1 R141.1 R149.1 U7.34 | length 896.8
  Top w5: R149.1@8440,-860 R141.1@8440,-900 R140.1@8480,-900 8480,-860 8495,-845 8570,-845 8585,-860 8844.14,-860 8889.14,-905 9100,-905 9149.88,-855.12 U7.34@9205.04,-855.12
CGE0_LED1: R135.1 R136.1 R152.1 U7.35 | length 664.4
  Top w5: R136.1@8600,-900 8635,-900 R135.1@8637.5,-897.5 ; R135.1@8640,-900 R152.1@8680,-900 8680,-880 8690,-870 8840,-870 8885,-915 9110,-915 9153.5,-871.5 U7.35@9205.04,-871.5
CGE0_LED2: R160.1 R161.1 U7.32 | length 575.3
  Top w5: R160.1@8680,-825 8837.43,-825 8897.43,-885 9080,-885 9141.38,-823.62 U7.32@9205.04,-823.62
CGE0_PME: R147.1 R148.1 U7.33 | length 662.9
  Top w5: R148.1@8600,-825 R147.1@8640,-825 8640,-835 8655,-850 8848.28,-850 8893.28,-895 9090,-895 9145.63,-839.37 U7.33@9205.04,-839.37
CGE0_RXCLK: R124.2 U7.19 | length 216.5
  Top w5: R124.2@9205,-555 9205,-575 9220,-590 9290,-590 9312.13,-612.13 U7.19@9312.13,-685.04 ; U7.19@9311.83,-685.34 9312.17,-685.67 U7.19@9312.17,-685.04
CGE0_RXCTL: R125.2 R153.1 U7.13 | length 185.3
  Top w5: U7.13@9406.65,-685.67 9406.65,-685.04 9406.65,-648.35 9430,-625 R153.1@9430,-555 R125.2@9475,-555
CGE0_RXD0: R126.2 R156.1 R158.1 U7.14 | length 299.3
  Top w5: U7.14@9390.91,-685.67 U7.14@9390.87,-685.04 9390.91,-644.09 9400,-635 9400,-590 9385,-575 R158.1@9385,-555 9407,-533 9407,-483 R126.2@9430,-460 R156.1@9475,-460
CGE0_RXD1: R127.2 R162.1 R164.1 U7.16 | length 296.9
  Top w5: U7.16@9359.41,-685.67 U7.16@9359.37,-685.04 9359.41,-594.41 9340,-575 R164.1@9340,-555 9362,-533 9362,-482 R127.2@9340,-460 R162.1@9385,-460
CGE0_RXD2: R128.2 R165.1 R167.1 U7.17 | length 309.1
  Top w5: R165.1@9250,-460 R128.2@9295,-460 9317,-482 9317,-533 R167.1@9295,-555 9343.66,-603.66 9343.66,-685.04 U7.17@9343.66,-685.67
CGE0_RXD3: R130.2 R168.1 R169.1 U7.18 | length 347.9
  Top w5: R168.1@9160,-460 R130.2@9205,-460 9228,-483 9228,-533 R169.1@9250,-555 9250,-575 9255,-580 9300,-580 9327.91,-607.91 U7.18@9327.87,-685.04 U7.18@9327.91,-685.67
CMAC_MDC: C100.2 R150.1 R157.2 U7.30 | length 309.6
  Top w5: R150.1@8955,-705 R157.2@8955,-745 9070,-745 9117.13,-792.13 U7.30@9205.04,-792.13
CMAC_MDIO: C101.2 R151.1 R159.2 U7.31 | length 299.5
  Top w5: R151.1@8955,-825 R159.2@8955,-785 8960,-790 C101.2@9000,-790 9085,-790 9102.87,-807.87 U7.31@9205.04,-807.87
CPHY105: B8.1 C76.1 C77.1 C78.1 U7.3 U7.9 U7.40 | length 725.2
  Top w8: v1(9266.46,-963.54) 9280.67,-949.33 U7.40@9280.67,-915.59 ; U7.3@9434.96,-855.12 9459.37,-855.12 9474.25,-870 v1(9490,-870) ; U7.9@9434.96,-760.63 9489.37,-760.63 v1(9495,-755)
  Top w15: v1(9490,-950) 9515.47,-950 9519.97,-954.5 B8.1@9520.47,-955
  Bottom w12: v1(9266.46,-963.54) 9268,-962 C76.1@9268,-937 9281,-950 v1(9490,-950) v1(9490,-870) 9520,-840 9520,-785 v1@9495,-760 ; C78.1@9468.98,-750 C78.1@9464.49,-745.51 9480.51,-745.51 9492.5,-757.5 v1@9495,-760 ; v1(9495,-755) v1@9495,-760
CRGMII_RXCK: JP3.C11 R124.1 | length 725.6
  Top w5: R124.1@9205,-515 9205,-513 9218,-500 9218,-493 9215,-490 9125,-490 9120,-485 9120,-475 9130,-465 9130,-460 9120,-450 9120,-440 9130,-430 9130,-415 9140,-405 9140,-395 9130,-385 9130,-375 9140,-365 9195.75,-365 ccw(c9195.75,-358.25) 9202.5,-358.25 9202.5,-346.75 cw(c9209.25,-346.75) 9209.25,-340 9210.75,-340 cw(c9210.75,-346.75) 9217.5,-346.75 9217.5,-358.25 ccw(c9224.25,-358.25) 9224.25,-365 9272.52,-365 9310,-327.52 9310,-279.14 9305.86,-275 9230.31,-275 9229.48,-275.82 9229.18,-275.82 9215,-290 9215,-310 9225,-320 9261.1,-320 JP3.C11@9265.75,-315.35
CRGMII_RXD0: JP3.C7 R126.1 | length 640.6
  Top w5: R126.1@9430,-420 v1@9430,-380
  Bottom w5: JP3.C7@8865.75,-315.35 8925.39,-375 9280,-375 9291.5,-386.5 9323.5,-386.5 9335,-375 v1(9430,-375) ; v1@9428.5,-378.5 v1@9430,-380
CRGMII_RXD1: JP3.C8 R127.1 | length 640.4
  Top w5: v1(9325,-355) 9340,-370 R127.1@9340,-420
  Bottom w5: JP3.C8@8965.75,-315.35 8930.35,-315.35 8925,-310 8925,-275 8935,-265 9320,-265 9325,-270 v1(9325,-355)
CRGMII_RXD2: JP3.C9 R128.1 | length 630.3
  Top w5: R128.1@9295,-420 9295,-380 v1(9305,-370)
  Bottom w5: JP3.C9@9065.75,-315.35 9070,-311.1 9070,-280 9065,-275 9030,-275 9020,-285 9020,-360 9025,-365 9100.75,-365 ccw(c9100.75,-358.25) 9107.5,-358.25 9107.5,-341.75 cw(c9114.25,-341.75) 9114.25,-335 9115.75,-335 cw(c9115.75,-341.75) 9122.5,-341.75 9122.5,-362.5 ccw(c9125,-362.5) 9125,-365 9200.75,-365 ccw(c9200.75,-358.25) 9207.5,-358.25 9207.5,-331.75 cw(c9214.25,-331.75) 9214.25,-325 9215.75,-325 cw(c9215.75,-331.75) 9222.5,-331.75 9222.5,-358.25 ccw(c9229.25,-358.25) 9229.25,-365 9285,-365 9290,-370 v1(9305,-370)
CRGMII_RXD3: JP3.C10 R130.1 | length 581.5
  Top w5: JP3.C10@9165.75,-315.35 9130.35,-315.35 9125,-310 9125,-275 9135,-265 9200.75,-265 ccw(c9200.75,-258.25) 9207.5,-258.25 9207.5,-246.75 cw(c9214.25,-246.75) 9214.25,-240 9215.75,-240 cw(c9215.75,-246.75) 9222.5,-246.75 9222.5,-262.5 ccw(c9225,-262.5) 9225,-265 9310,-265 9320,-275 9320,-331.67 9276.67,-375 9190,-375 9185,-380 9185,-400 R130.1@9205,-420
CRGMII_RXDV: JP3.C12 R125.1 | length 750.2
  Top w5: JP3.C12@9365.75,-315.35 9365.75,-279.25 9375,-270 9505,-270 9515,-280 9515,-365.75 ccw(c9521.75,-365.75) 9521.75,-372.5 9583.25,-372.5 cw(c9583.25,-379.25) 9590,-379.25 9590,-380.75 cw(c9583.25,-380.75) 9583.25,-387.5 9517.5,-387.5 ccw(c9517.5,-390) 9515,-390 9515,-405.75 ccw(c9521.75,-405.75) 9521.75,-412.5 9563.25,-412.5 cw(c9563.25,-419.25) 9570,-419.25 9570,-420.75 cw(c9563.25,-420.75) 9563.25,-427.5 9517.5,-427.5 ccw(c9517.5,-430) 9515,-430 9515,-445.75 ccw(c9521.75,-445.75) 9521.75,-452.5 9538.25,-452.5 cw(c9538.25,-459.25) 9545,-459.25 9545,-460.75 cw(c9538.25,-460.75) 9538.25,-467.5 9517.5,-467.5 ccw(c9517.5,-470) 9515,-470 9515,-500 9500,-515 R125.1@9475,-515
CRGMII_TXCKOUT: JP3.A11 U7.22 | length 1412
  Top w5: U7.22@9264.92,-685.67 U7.22@9264.88,-685.04 9264.92,-664.92 9240,-640 9150,-640 9081.21,-571.21 cw(c9086.52,-565.91) 9081.21,-560.61 9095.36,-546.46 ccw(c9090.05,-541.16) 9095.36,-535.86 ccw(c9090.05,-541.16) 9084.75,-535.85 9070.61,-550 cw(c9065.3,-544.7) 9060,-550 9055,-545 9055,-525 ccw(c9047.5,-525) 9047.5,-517.5 9037.5,-517.5 cw(c9037.5,-510) 9030,-510 cw(c9037.5,-510) 9037.5,-502.5 9082.5,-502.5 ccw(c9082.5,-495) 9090,-495 ccw(c9082.5,-495) 9082.5,-487.5 9062.5,-487.5 cw(c9062.5,-480) 9055,-480 cw(c9062.5,-480) 9062.5,-472.5 9082.5,-472.5 ccw(c9082.5,-465) 9090,-465 ccw(c9082.5,-465) 9082.5,-457.5 9062.5,-457.5 cw(c9062.5,-450) 9055,-450 cw(c9062.5,-450) 9062.5,-442.5 9082.5,-442.5 ccw(c9082.5,-435) 9090,-435 ccw(c9082.5,-435) 9082.5,-427.5 9062.5,-427.5 cw(c9062.5,-420) 9055,-420 9055,-395 9114.62,-335.38 9114.62,-175.38 9125,-165 9185,-165 ccw(c9185,-157.5) 9192.5,-157.5 9192.5,-150.91 cw(c9200,-150.91) 9200,-143.41 cw(c9200,-150.91) 9207.5,-150.91 9207.5,-187.64 ccw(c9215,-187.64) 9215,-195.14 ccw(c9215,-187.64) 9222.5,-187.64 9222.5,-172.5 cw(c9230,-172.5) 9230,-165 9305,-165 9315,-155 9315,-86.85 9295,-66.85 9270,-66.85 9265,-71.85 9265,-114.61 JP3.A11@9265.75,-115.35
CRGMII_TXD0: JP3.A7 U7.23 | length 1422.7
  Top w5: v1(9030,-165) 9030,-170 9020,-180 9020,-250 ccw(c9027.5,-250) 9027.5,-257.5 9047.5,-257.5 cw(c9047.5,-265) 9055,-265 cw(c9047.5,-265) 9047.5,-272.5 9027.5,-272.5 ccw(c9027.5,-280) 9020,-280 9020,-360 ccw(c9027.5,-360) 9027.5,-367.5 9047.5,-367.5 cw(c9047.5,-375) 9055,-375 cw(c9047.5,-375) 9047.5,-382.5 9027.5,-382.5 ccw(c9027.5,-390) 9020,-390 9020,-435 ccw(c9027.5,-435) 9027.5,-442.5 9037.5,-442.5 cw(c9037.5,-450) 9045,-450 cw(c9037.5,-450) 9037.5,-457.5 9027.5,-457.5 ccw(c9027.5,-465) 9020,-465 ccw(c9027.5,-465) 9027.5,-472.5 9037.5,-472.5 cw(c9037.5,-480) 9045,-480 cw(c9037.5,-480) 9037.5,-487.5 9027.5,-487.5 ccw(c9027.5,-495) 9020,-495 9020,-524.14 9145.86,-650 9235,-650 9249.17,-664.17 9249.17,-685.04 U7.23@9249.17,-685.67
  Bottom w5: JP3.A7@8865.75,-115.35 8904.65,-115.35 8910,-110 8910,-65 8900,-55 8825,-55 8815,-65 8815,-170 8825,-180 8840,-180 8855,-165 8900,-165 ccw(c8900,-157.5) 8907.5,-157.5 8907.5,-147.5 cw(c8915,-147.5) 8915,-140 cw(c8915,-147.5) 8922.5,-147.5 8922.5,-157.5 ccw(c8930,-157.5) 8930,-165 v1(9030,-165)
CRGMII_TXD1: JP3.A8 U7.24 | length 1412
  Top w5: JP3.A8@8965.75,-115.35 9010,-159.61 9010,-395 cw(c9005,-395) 9005,-400 8962.09,-400 ccw(c8962.09,-405) 8957.09,-405 ccw(c8962.09,-405) 8962.09,-410 9005,-410 cw(c9005,-415) 9010,-415 cw(c9005,-415) 9005,-420 8962.09,-420 ccw(c8962.09,-425) 8957.09,-425 ccw(c8962.09,-425) 8962.09,-430 9005,-430 cw(c9005,-435) 9010,-435 cw(c9005,-435) 9005,-440 8935,-440 ccw(c8935,-445) 8930,-445 ccw(c8935,-445) 8935,-450 9005,-450 cw(c9005,-455) 9010,-455 cw(c9005,-455) 9005,-460 8951.21,-460 ccw(c8951.21,-465) 8946.21,-465 ccw(c8951.21,-465) 8951.21,-470 9005,-470 cw(c9005,-475) 9010,-475 cw(c9005,-475) 9005,-480 8971.21,-480 ccw(c8971.21,-485) 8966.21,-485 ccw(c8971.21,-485) 8971.21,-490 9005,-490 cw(c9005,-495) 9010,-495 cw(c9005,-495) 9005,-500 8991.21,-500 ccw(c8991.21,-505) 8986.21,-505 ccw(c8991.21,-505) 8991.21,-510 9005,-510 cw(c9005,-515) 9010,-515 9010,-528.28 9141.72,-660 9175,-660 cw(c9175,-665) 9180,-665 9180,-685.04 ccw(c9185,-685.04) 9185,-690.04 ccw(c9185,-685.04) 9190,-685.04 9190,-665 cw(c9195,-665) 9195,-660 cw(c9195,-665) 9200,-665 9200,-683.14 ccw(c9205,-683.14) 9205,-688.14 ccw(c9205,-683.14) 9210,-683.14 9210,-665 cw(c9215,-665) 9215,-660 9225,-660 9233.43,-668.43 U7.24@9233.39,-685.04 U7.24@9233.43,-685.67
CRGMII_TXD2: JP3.A9 U7.25 | length 1412
  Top w5: JP3.A9@9065.75,-115.35 9084.65,-115.35 9098.85,-101.15 9098.85,-81.15 9094.56,-76.85 9030,-76.85 ccw(c9030,-84.35) 9022.5,-84.35 9022.5,-109.35 cw(c9015,-109.35) 9015,-116.85 cw(c9015,-109.35) 9007.5,-109.35 9007.5,-84.35 ccw(c9000,-84.35) 9000,-76.85 8933.15,-76.85 8920,-90 8920,-153 ccw(c8924.5,-153) 8924.5,-157.5 8955.5,-157.5 cw(c8955.5,-162) 8960,-162 8960,-168 cw(c8955.5,-168) 8955.5,-172.5 8922.5,-172.5 ccw(c8922.5,-175) 8920,-175 8920,-250 ccw(c8927.5,-250) 8927.5,-257.5 8952.5,-257.5 cw(c8952.5,-265) 8960,-265 cw(c8952.5,-265) 8952.5,-272.5 8927.5,-272.5 ccw(c8927.5,-280) 8920,-280 8920,-355 ccw(c8927.5,-355) 8927.5,-362.5 8987.5,-362.5 cw(c8987.5,-370) 8995,-370 cw(c8987.5,-370) 8987.5,-377.5 8927.5,-377.5 ccw(c8927.5,-385) 8920,-385 8920,-405 ccw(c8925,-405) 8925,-410 8944.77,-410 cw(c8944.77,-415) 8949.77,-415 cw(c8944.77,-415) 8944.77,-420 8925,-420 ccw(c8925,-425) 8920,-425 8920,-455 9110,-645 ; 9100,-635 9110,-645 ; U7.25@9205.04,-714.02 9179.02,-714.02 9110,-645
CRGMII_TXD3: JP3.A10 U7.26 | length 1412
  Top w5: JP3.A10@9165.75,-115.35 9170.39,-120 9210,-120 9220,-110 9220,-80 9206.85,-66.85 9134.25,-66.85 ccw(c9134.25,-73.6) 9127.5,-73.6 9127.5,-90.1 cw(c9120.75,-90.1) 9120.75,-96.85 9119.25,-96.85 cw(c9119.25,-90.1) 9112.5,-90.1 9112.5,-73.6 ccw(c9105.75,-73.6) 9105.75,-66.85 8929,-66.85 8910,-85.86 8910,-365.75 cw(c8903.25,-365.75) 8903.25,-372.5 8841.75,-372.5 ccw(c8841.75,-379.25) 8835,-379.25 8835,-380.75 ccw(c8841.75,-380.75) 8841.75,-387.5 8903.25,-387.5 cw(c8903.25,-394.25) 8910,-394.25 8910,-415 cw(c8905,-415) 8905,-420 8896.57,-420 ccw(c8896.57,-425) 8891.57,-425 ccw(c8896.57,-425) 8896.57,-430 8905,-430 cw(c8905,-435) 8910,-435 8910,-464.02 9170,-724.02 9184.02,-724.02 9189.76,-729.76 U7.26@9205.04,-729.76
CRGMII_TXEN: JP3.A12 U7.27 | length 1412
  Top w5: U7.27@9205.04,-745.51 9190.51,-745.51 9179.02,-734.02 9165.86,-734.02 8820,-388.16 8820,-95 8858.15,-56.85 9307.25,-56.85 JP3.A12@9365.75,-115.35
CUART1_RXD: J3.19 R172.2 R208.1 R210.1 | length 4388.3
  Top w5: v1(4540,-420) 4530,-430 4530,-805 4820,-1095 4820,-1178.27 J3.19@4862.21,-1220.47 ; v1@6421.81,16.5 6442.31,37 7213.14,37 7280.14,-30 7305,-30 R208.1@7340,5
  Top w8: R208.1@7340,5 R210.1@7385,5 R172.2@7385,-35
  Bottom w5: v1@4545,-415 4545,-370 4535,-360 4535,-85 4618,-2 5871.14,-2 6034.14,-165 6238,-165 v1@6417,14
  other v1: 6421.31,17
CUART1_TXD: J3.20 R173.2 R209.1 R211.1 | length 4293.3
  Top w5: v1(4565,-420) 4540,-445 4540,-795 4862.21,-1117.21 J3.20@4862.21,-1141.73 ; 6456,27 7209,27 7276,-40 7310,-40 R209.1@7345,-75
  Top w8: R209.1@7345,-75 R173.2@7385,-75 R211.1@7385,-115
  Bottom w5: v1(4565,-420) 4565,-375 4545,-355 4545,-89.14 4622.14,-12 5867,-12 6030,-175 6257,-175 v1@6445,13
  other v1: 6449,20
EPHY_CLK: JP1.A13 R16.1 | length 2315.9
  Top w8: v1(5165,-610) 5110,-555 5055,-555 4840,-340 4840,-60 4875,-25 5546,-25 5587.8,-66.8 JP1.A13@5587.8,-115.35 ; v1(5190,-980) 5285,-1075 5485,-1075 5500,-1060 R16.1@5500,-1025
  Bottom w8: v1(5165,-610) 5165,-955 v1(5190,-980)
EPHY_RSTN: JP1.A5 R12.1 | length 663.9
  Top w5: JP1.A5@4787.8,-115.35 4740,-163.15 4740,-370 4980,-610 R12.1@5030,-610
GE0_ENREG: R25.1 U1.38 | length 106.2
  Top w5: R25.1@5420,-985 5420,-950 5444.93,-925.07 U1.38@5444.93,-889.17
GE0_INT_N: R23.1 U1.20 | length 230.7
  Top w5: R23.1@5360,-539 5360,-560 5378.5,-578.5 5473.5,-578.5 5492.18,-597.18 U1.20@5492.18,-659.25
GE0_LED0: R19.1 R21.1 R29.1 U1.34 | length 1045.2
  Top w5: U1.34@5400.84,-829.33 5324.81,-829.33 5244.14,-910 5140,-910 5125,-925 5125,-1025 5340,-1240 R21.1@5515,-1240 R29.1@5515,-1280 5485,-1310 5485,-1340 5505,-1360 R19.1@5515,-1360
GE0_LED1: R14.1 R15.1 R32.1 U1.35 | length 1119.8
  Top w5: U1.35@5400.84,-845.08 5399.43,-843.68 5324.61,-843.68 5248.28,-920 5144.14,-920 5135,-929.14 5135,-1020.86 5284.14,-1170 5640,-1170 5675,-1205 R15.1@5705,-1205 R14.1@5705,-1285
GE0_LED2: R40.1 R41.1 U1.32 | length 398.2
  Top w5: R40.1@5085,-940 R41.1@5085,-900 5115,-900 5125,-890 5235,-890 5327.17,-797.83 U1.32@5400.84,-797.83
GE0_PME: R27.1 R28.1 U1.33 | length 441.8
  Top w5: R28.1@5085,-1020 R27.1@5085,-980 5115,-950 5115,-920.86 5135.86,-900 5240,-900 5326.42,-813.58 U1.33@5400.84,-813.58
GE0_RXCLK: R4.2 U1.19 | length 190.4
  Top w5: R4.2@5405,-539 5434.5,-568.5 5481.43,-568.5 5507.93,-595 U1.19@5507.93,-659.25
GE0_RXCTL: R5.2 R33.1 U1.13 | length 176.7
  Top w5: U1.13@5602.41,-659.25 5602.41,-622.59 5605,-620 5605,-580 5630,-555 R33.1@5630,-539 R5.2@5675,-539
GE0_RXD0: R6.2 R36.1 R38.1 U1.14 | length 295.5
  Top w5: U1.14@5586.67,-659.25 5586.67,-618.33 5595,-610 R38.1@5595,-549 ; R38.1@5595,-535 R38.1@5595,-549 ; R6.2@5675,-449 R36.1@5630,-449 5607,-472 5607,-517 R38.1@5585,-539 R38.1@5595,-549
GE0_RXD1: R7.2 R43.1 R44.1 U1.16 | length 278.9
  Top w5: U1.16@5555.17,-659.25 5555.17,-576 5540,-560.83 R44.1@5540,-539 5519,-518 5519,-470 R7.2@5540,-449 R43.1@5585,-449
GE0_RXD2: R8.2 R45.1 R47.1 U1.17 | length 291.9
  Top w5: R45.1@5450,-449 R8.2@5495,-449 5473,-471 5473,-517 R47.1@5495,-539 5495,-552.58 5539.42,-597 U1.17@5539.42,-659.25
GE0_RXD3: R9.2 R48.1 R49.1 U1.18 | length 315.9
  Top w5: R48.1@5360,-449 R9.2@5405,-449 5428,-472 5428,-517 R49.1@5450,-539 ; R49.1@5452.07,-539 R49.1@5450,-539 ; U1.18@5523.67,-659.25 5523.67,-596.6 5485.57,-558.5 5469.5,-558.5 R49.1@5450,-539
